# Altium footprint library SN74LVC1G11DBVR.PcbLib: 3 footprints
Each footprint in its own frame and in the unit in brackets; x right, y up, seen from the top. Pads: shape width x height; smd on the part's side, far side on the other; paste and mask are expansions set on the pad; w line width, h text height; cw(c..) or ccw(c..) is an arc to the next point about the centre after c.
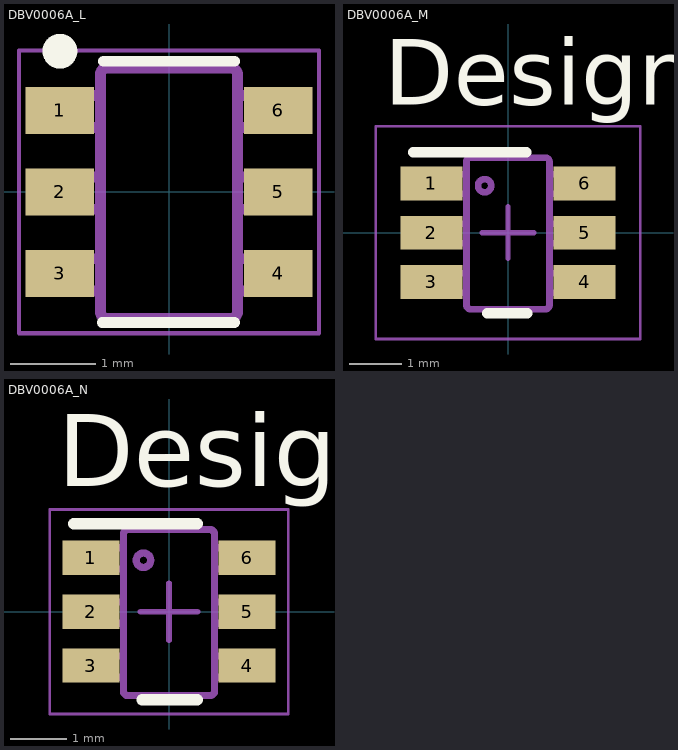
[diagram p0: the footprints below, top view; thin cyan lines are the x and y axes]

## DBV0006A_L [mm]
pads (6):
  rect 0.8x0.55 smd paste+0 mask+0.051: 1(-1.275,0.95) 2(-1.275,0) 3(-1.275,-0.95) 4(1.275,-0.95) 5(1.275,0) 6(1.275,0.95)
Top Overlay:
  lines w0.127: -0.779,-1.525 0.762,-1.524 ; -0.762,1.524 0.762,1.524
  lines w0.254: -1.349,1.642 ccw(c-1.273,1.642) -1.197,1.642 ccw(c-1.273,1.642) -1.349,1.642
Mechanical 13:
  lines w0.127: 0.724,-1.475 ccw(c0.723,-1.399) 0.8,-1.399 0.8,1.37 ccw(c0.723,1.37) 0.724,1.446 ; 0.723,-1.475 0.724,-1.475 ; 0.723,-1.475 -0.724,-1.475 -0.725,-1.475 cw(c-0.724,-1.399) -0.801,-1.399 -0.801,1.37 cw(c-0.724,1.37) -0.725,1.446 -0.724,1.446 0.723,1.446 ; 0.723,1.446 0.724,1.446 ; -1.423,-1.154 -1.206,-1.154 -1.113,-1.154 -1.081,-1.154 -0.828,-1.154 -0.801,-1.154 -0.801,-0.78 -0.828,-0.78 -1.081,-0.78 -1.113,-0.78 -1.206,-0.78 -1.423,-0.78 -1.423,-1.154 ; -1.423,-0.202 -1.206,-0.202 -1.113,-0.202 -1.081,-0.202 -0.828,-0.202 -0.801,-0.202 -0.801,0.173 -0.828,0.173 -1.081,0.173 -1.113,0.173 -1.206,0.173 -1.423,0.173 -1.423,-0.202 ; -1.423,0.751 -1.206,0.751 -1.113,0.751 -1.081,0.751 -0.828,0.751 -0.801,0.751 -0.801,1.125 -0.828,1.125 -1.081,1.125 -1.113,1.125 -1.206,1.125 -1.423,1.125 -1.423,0.751 ; 0.8,-1.154 0.827,-1.154 1.08,-1.154 1.112,-1.154 1.205,-1.154 1.422,-1.154 1.422,-0.78 1.205,-0.78 1.112,-0.78 1.08,-0.78 0.827,-0.78 0.8,-0.78 0.8,-1.154 ; 0.8,-0.202 0.827,-0.202 1.08,-0.202 1.112,-0.202 1.205,-0.202 1.422,-0.202 1.422,0.173 1.205,0.173 1.112,0.173 1.08,0.173 0.827,0.173 0.8,0.173 0.8,-0.202 ; 0.8,0.751 0.827,0.751 1.08,0.751 1.112,0.751 1.205,0.751 1.422,0.751 1.422,1.125 1.205,1.125 1.112,1.125 1.08,1.125 0.827,1.125 0.8,1.125 0.8,0.751
Mechanical 15:
  lines w0.05: -1.75,-1.65 1.75,-1.65 1.75,1.65 -1.75,1.65 -1.75,-1.65

## DBV0006A_M [mm]
pads (6):
  rect 1.2x0.65 smd paste+0 mask+0.051: 1(-1.475,0.95) 2(-1.475,0) 3(-1.475,-0.95) 4(1.475,-0.95) 5(1.475,0) 6(1.475,0.95)
Top Overlay:
  lines w0.2: -1.825,1.55 0.35,1.55 ; -0.4,-1.55 0.375,-1.55
  text "Designator9" at -2.388,2.464 h1.27
  text ".Designator" at -3.492,-0.635 h1.27
Mechanical 13:
  lines w0.127: 0.723,-1.475 -0.724,-1.475 -0.725,-1.475 cw(c-0.724,-1.399) -0.801,-1.399 -0.801,1.37 cw(c-0.724,1.37) -0.725,1.446 -0.724,1.446 0.723,1.446 ; 0.723,-1.475 0.724,-1.475 ; 0.724,-1.475 ccw(c0.723,-1.399) 0.8,-1.399 0.8,1.37 ccw(c0.723,1.37) 0.724,1.446 ; 0.723,1.446 0.724,1.446 ; -1.423,-1.154 -1.423,-0.78 -1.206,-0.78 -1.113,-0.78 -1.081,-0.78 -0.828,-0.78 -0.801,-0.78 -0.801,-1.154 -0.828,-1.154 -1.081,-1.154 -1.113,-1.154 -1.206,-1.154 -1.423,-1.154 ; -1.423,-0.202 -1.423,0.173 -1.206,0.173 -1.113,0.173 -1.081,0.173 -0.828,0.173 -0.801,0.173 -0.801,-0.202 -0.828,-0.202 -1.081,-0.202 -1.113,-0.202 -1.206,-0.202 -1.423,-0.202 ; -1.423,0.751 -1.423,1.125 -1.206,1.125 -1.113,1.125 -1.081,1.125 -0.828,1.125 -0.801,1.125 -0.801,0.751 -0.828,0.751 -1.081,0.751 -1.113,0.751 -1.206,0.751 -1.423,0.751 ; -0.577,0.906 ccw(c-0.45,0.906) -0.323,0.906 ccw(c-0.45,0.906) -0.577,0.906 ; 0.8,-1.154 0.8,-0.78 0.827,-0.78 1.08,-0.78 1.112,-0.78 1.205,-0.78 1.422,-0.78 1.422,-1.154 1.205,-1.154 1.112,-1.154 1.08,-1.154 0.827,-1.154 0.8,-1.154 ; 0.8,-0.202 0.8,0.173 0.827,0.173 1.08,0.173 1.112,0.173 1.205,0.173 1.422,0.173 1.422,-0.202 1.205,-0.202 1.112,-0.202 1.08,-0.202 0.827,-0.202 0.8,-0.202 ; 0.8,0.751 0.8,1.125 0.827,1.125 1.08,1.125 1.112,1.125 1.205,1.125 1.422,1.125 1.422,0.751 1.205,0.751 1.112,0.751 1.08,0.751 0.827,0.751 0.8,0.751
  text ".Designator" at -3.492,-0.635 h1.27
Mechanical 15:
  lines w0.05: -2.55,-2.05 -2.55,2.05 2.55,2.05 2.55,-2.05 -2.55,-2.05
  lines w0.1: -0.5,0 0.5,0 ; 0,-0.5 0,0.5

## DBV0006A_N [mm]
pads (6):
  rect 1x0.6 smd paste+0 mask+0.051: 1(-1.375,0.95) 2(-1.375,0) 3(-1.375,-0.95) 4(1.375,-0.95) 5(1.375,0) 6(1.375,0.95)
Top Overlay:
  lines w0.2: -1.675,1.55 0.5,1.55 ; -0.475,-1.55 0.5,-1.55
  text "Designator9" at -1.956,2.21 h1.27
  text ".Designator" at -3.492,-0.635 h1.27
Mechanical 13:
  lines w0.127: 0.723,-1.475 0.724,-1.475 ; 0.723,-1.475 -0.724,-1.475 -0.725,-1.475 cw(c-0.724,-1.399) -0.801,-1.399 -0.801,1.37 cw(c-0.724,1.37) -0.725,1.446 -0.724,1.446 0.723,1.446 ; 0.724,-1.475 ccw(c0.723,-1.399) 0.8,-1.399 0.8,1.37 ccw(c0.723,1.37) 0.724,1.446 ; 0.723,1.446 0.724,1.446 ; -1.423,-1.154 -1.206,-1.154 -1.113,-1.154 -1.081,-1.154 -0.828,-1.154 -0.801,-1.154 -0.801,-0.78 -0.828,-0.78 -1.081,-0.78 -1.113,-0.78 -1.206,-0.78 -1.423,-0.78 -1.423,-1.154 ; -1.423,-0.202 -1.206,-0.202 -1.113,-0.202 -1.081,-0.202 -0.828,-0.202 -0.801,-0.202 -0.801,0.173 -0.828,0.173 -1.081,0.173 -1.113,0.173 -1.206,0.173 -1.423,0.173 -1.423,-0.202 ; -1.423,0.751 -1.206,0.751 -1.113,0.751 -1.081,0.751 -0.828,0.751 -0.801,0.751 -0.801,1.125 -0.828,1.125 -1.081,1.125 -1.113,1.125 -1.206,1.125 -1.423,1.125 -1.423,0.751 ; -0.577,0.906 cw(c-0.45,0.906) -0.323,0.906 cw(c-0.45,0.906) -0.577,0.906 ; 0.8,-1.154 0.827,-1.154 1.08,-1.154 1.112,-1.154 1.205,-1.154 1.422,-1.154 1.422,-0.78 1.205,-0.78 1.112,-0.78 1.08,-0.78 0.827,-0.78 0.8,-0.78 0.8,-1.154 ; 0.8,-0.202 0.827,-0.202 1.08,-0.202 1.112,-0.202 1.205,-0.202 1.422,-0.202 1.422,0.173 1.205,0.173 1.112,0.173 1.08,0.173 0.827,0.173 0.8,0.173 0.8,-0.202 ; 0.8,0.751 0.827,0.751 1.08,0.751 1.112,0.751 1.205,0.751 1.422,0.751 1.422,1.125 1.205,1.125 1.112,1.125 1.08,1.125 0.827,1.125 0.8,1.125 0.8,0.751
  text ".Designator" at -3.492,-0.635 h1.27
Mechanical 15:
  lines w0.05: -2.1,-1.8 2.1,-1.8 2.1,1.8 -2.1,1.8 -2.1,-1.8
  lines w0.1: -0.5,0 0.5,0 ; 0,-0.5 0,0.5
